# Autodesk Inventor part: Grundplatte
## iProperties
Created: 2010-08
Part Number: Grundplatte
Document SubType Name: Modeling
Designer: Admin
Density: 1 g/cm^3
Author: Admin
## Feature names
1. Extrusion1
